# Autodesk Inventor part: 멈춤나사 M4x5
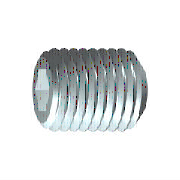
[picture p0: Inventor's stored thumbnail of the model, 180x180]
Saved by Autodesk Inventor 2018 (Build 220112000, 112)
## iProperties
IsCustomPart: 1
Created: 2012-02
Part Number: 멈춤나사 M4x5
Material: 강철, 연강
Description: 6각 소켓 머리 없는 멈춤 나사
Document SubType Name: Modeling
Standard: KS B 1028
Designer: mduedu
Standards Organization: KS
Language: ko-KR
Size Designation: 납작점M4x5
Categories: <MemberInstance><Categories><Category DisplayName="조임쇠" InternalName="e4da775c-781d-43d5-af7c-5136215cf5a6" Mnemonic="FSTN"><Category DisplayName="볼트" InternalN
Density: 1 g/cm^3
Appearance: 강철
Author: mduedu
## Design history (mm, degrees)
sketch "스케치1"
  geometry: L1 (0, 0)-(1.833, 0); L2 (5, 1.155)-(5, 2); L3 (5, 2)-(0, 2); L4 (5, 1.155)-(2.5, 1.155); L5 (2.5, 1.155)-(1.833, 0); L6 (0, -0.4)-(0, 2.4) reference; L7 (0, 2)-(0, 0)
  constraints: 13 end point, 3 parallel, 1 collinear, 1 perpendicular, 1 point on line
  dimensions: "d0" = 2.5 distance of L2.start L4.end (= INTI); "d1" = 60 deg angle of L5 L1; "d2" = 4 diameter of L3 L1 (= NND); "d3" = 2.3094 diameter of L4 L1 (= 1.1547 x SW); "d5" = 5 distance from line of L2 L3.end (= NLG)
revolve "본체" sketch "스케치1" stored, may be unused: angle "d6" = 90 deg
sketch "스케치2"
  geometry: L1 (-0.577, 1)-(0.577, 1); L2 (0.577, 1)-(1.155, 0); L3 (1.155, 0)-(0.577, -1); L4 (0.577, -1)-(-0.577, -1); L5 (-0.577, -1)-(-1.155, 0); L6 (-1.155, 0)-(-0.577, 1); A1 r 1.155 centre (0, 0) between (-0.577, 1) and (0.577, 1) reference; 2 further points
  constraints: 12 end point, 2 point on circle, 1 coincident, 1 horizontal, 11 other
extrude "슬롯" join sketch "스케치2" taper "d9" = 0 deg; stored distance "d21" = 10
workaxis "Work Axis1"
workplane "Work Plane1"
body "Solid1"
chamfer "모따기1" distance "d7" = 0.42941 (= -0.5 x GD1 + 0.5 x NND); stored, may be unused: angle "d8" = 45 deg (= FAWI), second distance "d29" = 0.42941 (= -0.5 x GD1 + 0.5 x NND)
feature "스레드" dims "d11" = 5 (= NLG), "d12" = 0
chamfer "모따기2" distance "d13" = 0.42941 (= -0.5 x GD1 + 0.5 x NND); stored, may be unused: angle "d14" = 45 deg (= FAWI), second distance "d30" = 0.42941 (= -0.5 x GD1 + 0.5 x NND)
other parameters: "NND" = 4 [user parameter; used in 5 equation terms], "NLG" = 5 [user parameter; used in 2 equation terms], "INTI" = 2.5 [user parameter; used in 1 equation term], "FAWI" = 45 deg [user parameter; used in 2 equation terms], "SW" = 2 [user parameter; used in 2 equation terms], "GD1" = 3.14117 (= THREADDIA - 1.2269 x PTC) [user parameter; used in 4 equation terms], "d4" = 0, "FAWI1" = 45 deg [user parameter], "d15" = 0, "d31" = 0, "GUL" = 0.42941 (= 0.61345 x PTC) [user parameter], "SPD" = 2.5 [user parameter], "TPU" = 14.28571 (computed from PTC) [user parameter], "TOA" = 30 deg [user parameter], "THREADDIA" = 4 [user parameter; used in 1 equation term], "PTC" = 0.7 [user parameter; used in 4 equation terms], "GAL" = 0.42941 (= 0.61345 x PTC) [user parameter], "E0" = 2.31 (= 1.155 x SW) [user parameter]
